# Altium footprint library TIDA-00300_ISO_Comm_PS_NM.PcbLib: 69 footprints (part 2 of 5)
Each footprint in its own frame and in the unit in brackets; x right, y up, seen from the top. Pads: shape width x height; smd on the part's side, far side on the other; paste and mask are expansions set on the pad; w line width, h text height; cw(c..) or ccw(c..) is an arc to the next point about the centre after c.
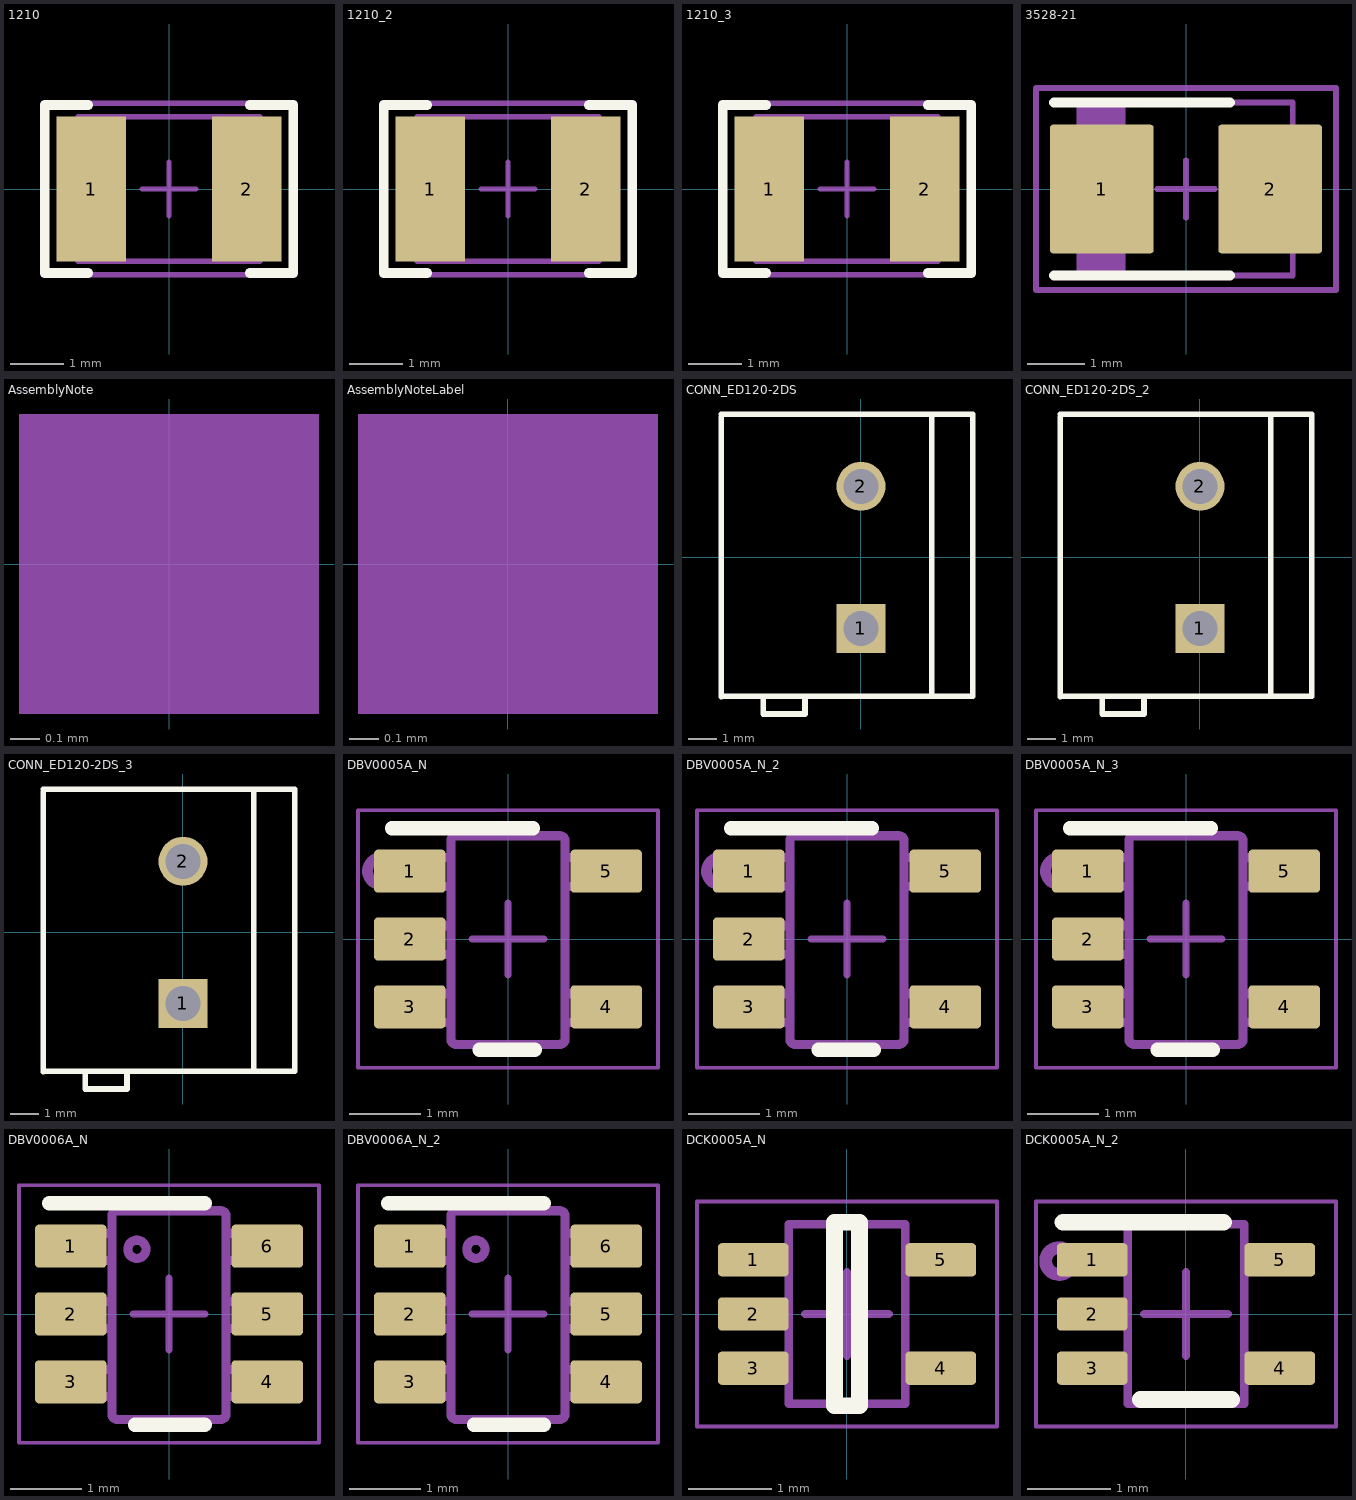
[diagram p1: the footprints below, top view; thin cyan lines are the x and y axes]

## 1210 [mm] "1210 from SM-752 data"
height 1.35
pads (2):
  rect 1.3x2.7 smd: 1(-1.45,0) 2(1.45,0)
Top Overlay:
  lines w0.178: -1.511,-1.568 -2.316,-1.568 -2.316,1.568 -1.511,1.568 ; 1.511,-1.568 2.316,-1.568 2.316,1.568 1.511,1.568
Mechanical 5:
  lines w0.1: -1.7,-1.35 -1.7,1.35 1.7,1.35 1.7,-1.35 -1.7,-1.35
  text ".Designator" at 0.229,-0.711 h0.51
Mechanical 13:
  lines w0.1: -1.2,-1.35 -1.2,1.35 ; 1.2,-1.35 1.2,1.35 ; -1.7,-1.35 1.7,-1.35 1.7,1.35 -1.7,1.35 -1.7,-1.35
Mechanical 15:
  lines w0.1: -0.5,0 0.5,0 ; 0,-0.5 0,0.5 ; -2.35,-1.6 2.35,-1.6 2.35,1.6 -2.35,1.6 -2.35,-1.6
3D body: height 1.35, standoff 0, extent 1.201,-1.349 1.699,1.349
3D body: height 1.35, standoff 0, extent -1.199,-1.349 1.199,1.349
3D body: height 1.35, standoff 0, extent -1.699,-1.349 -1.201,1.349

## 1210_2 [mm]
pads (2):
  rect 1.3x2.7 smd: 1(-1.45,0) 2(1.45,0)
Top Overlay:
  lines w0.178: -1.511,-1.568 -2.316,-1.568 -2.316,1.568 -1.511,1.568 ; 1.511,-1.568 2.316,-1.568 2.316,1.568 1.511,1.568
Mechanical 5:
  lines w0.1: -1.7,-1.35 1.7,-1.35 1.7,1.35 -1.7,1.35 -1.7,-1.35
  text ".Designator" at 0.152,-0.688 h0.51
Mechanical 13:
  lines w0.1: -1.2,-1.35 -1.2,1.35 ; 1.2,-1.35 1.2,1.35 ; -1.7,-1.35 -1.7,1.35 1.7,1.35 1.7,-1.35 -1.7,-1.35
Mechanical 15:
  lines w0.1: -0.5,0 0.5,0 ; 0,-0.5 0,0.5 ; -2.35,-1.6 -2.35,1.6 2.35,1.6 2.35,-1.6 -2.35,-1.6
3D body: height 1.35, standoff 0, extent -1.699,-1.349 -1.201,1.349
3D body: height 1.35, standoff 0, extent -1.199,-1.349 1.199,1.349
3D body: height 1.35, standoff 0, extent 1.201,-1.349 1.699,1.349

## 1210_3 [mm]
pads (2):
  rect 1.3x2.7 smd: 1(-1.45,0) 2(1.45,0)
Top Overlay:
  lines w0.178: -1.511,-1.568 -2.316,-1.568 -2.316,1.568 -1.511,1.568 ; 1.511,-1.568 2.316,-1.568 2.316,1.568 1.511,1.568
Mechanical 5:
  lines w0.1: -1.7,-1.35 1.7,-1.35 1.7,1.35 -1.7,1.35 -1.7,-1.35
  text ".Designator" at -0.254,0.298 h0.51
Mechanical 13:
  lines w0.1: -1.2,-1.35 -1.2,1.35 ; 1.2,-1.35 1.2,1.35 ; -1.7,-1.35 -1.7,1.35 1.7,1.35 1.7,-1.35 -1.7,-1.35
Mechanical 15:
  lines w0.1: -0.5,0 0.5,0 ; 0,-0.5 0,0.5 ; -2.35,-1.6 -2.35,1.6 2.35,1.6 2.35,-1.6 -2.35,-1.6
3D body: height 1.35, standoff 0, extent -1.699,-1.349 -1.201,1.349
3D body: height 1.35, standoff 0, extent -1.199,-1.349 1.199,1.349
3D body: height 1.35, standoff 0, extent 1.201,-1.349 1.699,1.349

## 3528-21 [mm] "Medium Density IPC, based on Kemet datasheet 2016-10-20"
height 2.1
pads (2):
  rrect6% 1.8x2.23 smd: 1(-1.46,0) 2(1.46,0)
Top Overlay:
  lines w0.178: -2.286,-1.5 0.762,-1.5 ; -2.286,1.5 0.762,1.5
Mechanical 5:
  rectangle: -1.85,-1.5 -1.1,1.5
  lines w0.1: -1.1,-1.5 -1.1,1.5 ; -1.85,-1.5 1.85,-1.5 1.85,1.5 -1.85,1.5 -1.85,-1.5
  text ".Designator" at -0.254,-0.292 h0.51
Mechanical 15:
  lines w0.1: -0.5,0 0.5,0 ; 0,-0.5 0,0.5 ; -2.6,-1.75 -2.6,1.75 2.6,1.75 2.6,-1.75 -2.6,-1.75
3D body "3528-21.stp": height 2.12, standoff 0.01, extent -1.85,-1.5 1.85,1.5

## AssemblyNote [mm] "Assembly Note"
Mechanical 5:
  rectangle: -0.508,-0.508 0.508,0.508
  text ".Comment" at 1.143,-0.508 h0.51
  text ".Designator" at -4.191,-0.508 h0.51

## AssemblyNoteLabel [mm] "Assembly Note for PCB Labels"
Mechanical 5:
  rectangle: -0.508,-0.508 0.508,0.508
  text "Install label in silkscreened box after final wash.  Text shall be 8 pt font.  Text shall be per the Label Table in the PDF schematic." at 1.143,-0.508 h0.51
  text ".Designator" at -4.191,-0.508 h0.51

## CONN_ED120-2DS [mm] "ONSHORE"
height 13
pads (2):
  rect 1.75x1.75 hole 1.25: 1(0,-2.54)
  round 1.75 hole 1.25: 2(0,2.54)
Top Overlay:
  lines w0.2: -5,-4.985 -5,5.015 ; -5,-4.96 4,-4.96 ; -5,5.115 4,5.115 4,-4.885 ; -3.5,-4.96 -3.5,-5.6 -2,-5.6 -2,-4.96 ; 2.525,-4.95 2.525,5.05
Mechanical 5:
  circle w0.152: c0,-2.54 r0.458
  lines w0.1: -5,-4.96 4,-4.96 ; -5,-4.885 -5,5.115 4,5.115 4,-4.885 ; -3.5,-4.96 -3.5,-5.6 -2,-5.6 -2,-4.96 ; 2.525,-4.875 2.525,5.125
  text ".Designator" at -0.184,0.432 h0.51
3D body: height 13, standoff 0, extent -3.5,-5.6 -2,-4.925
3D body: height 5.7, standoff 4.3, extent -0.875,-3.204 4.125,-1.81
3D body: height 5.7, standoff 4.3, extent -0.85,1.846 4.15,3.24
3D body: height 13.1, standoff -2.5, extent -0.496,2.041 0.5,3.039
3D body: height 13.1, standoff -2.5, extent -0.496,-3.039 0.5,-2.041
3D body: height 13, standoff 0, extent -5,-4.985 4,5.115

## CONN_ED120-2DS_2 [mm]
pads (2):
  rect 1.75x1.75 hole 1.25: 1(0,-2.54)
  round 1.75 hole 1.25: 2(0,2.54)
Top Overlay:
  lines w0.2: -5,-4.985 -5,5.015 ; -5,-4.96 4,-4.96 ; -5,5.115 4,5.115 4,-4.885 ; -3.5,-4.96 -3.5,-5.6 -2,-5.6 -2,-4.96 ; 2.525,-4.95 2.525,5.05
Mechanical 5:
  circle w0.152: c0,-2.54 r0.458
  lines w0.1: -5,-4.96 4,-4.96 ; -5,-4.885 -5,5.115 4,5.115 4,-4.885 ; -3.5,-4.96 -3.5,-5.6 -2,-5.6 -2,-4.96 ; 2.525,-4.875 2.525,5.125
  text ".Designator" at -0.159,0.279 h0.51
3D body: height 13, standoff 0, extent -5,-4.985 4,5.115
3D body: height 13.1, standoff -2.5, extent -0.496,-3.039 0.5,-2.041
3D body: height 13.1, standoff -2.5, extent -0.496,2.041 0.5,3.039
3D body: height 5.7, standoff 4.3, extent -0.85,1.846 4.15,3.24
3D body: height 5.7, standoff 4.3, extent -0.875,-3.204 4.125,-1.81
3D body: height 13, standoff 0, extent -3.5,-5.6 -2,-4.925

## CONN_ED120-2DS_3 [mm]
pads (2):
  rect 1.75x1.75 hole 1.25: 1(0,-2.54)
  round 1.75 hole 1.25: 2(0,2.54)
Top Overlay:
  lines w0.2: -5,-4.985 -5,5.015 ; -5,-4.96 4,-4.96 ; -5,5.115 4,5.115 4,-4.885 ; -3.5,-4.96 -3.5,-5.6 -2,-5.6 -2,-4.96 ; 2.525,-4.95 2.525,5.05
Mechanical 5:
  circle w0.152: c0,-2.54 r0.458
  lines w0.1: -5,-4.96 4,-4.96 ; -5,-4.885 -5,5.115 4,5.115 4,-4.885 ; -3.5,-4.96 -3.5,-5.6 -2,-5.6 -2,-4.96 ; 2.525,-4.875 2.525,5.125
  text ".Designator" at 0.484,0.254 h0.51
3D body: height 13, standoff 0, extent -3.5,-5.6 -2,-4.925
3D body: height 5.7, standoff 4.3, extent -0.875,-3.204 4.125,-1.81
3D body: height 5.7, standoff 4.3, extent -0.85,1.846 4.15,3.24
3D body: height 13.1, standoff -2.5, extent -0.496,2.041 0.5,3.039
3D body: height 13.1, standoff -2.5, extent -0.496,-3.039 0.5,-2.041
3D body: height 13, standoff 0, extent -5,-4.985 4,5.115

## DBV0005A_N [mm] "SOT23, 5-Leads, Body 2.9x1.6mm, Pitch 0.95mm, Lead Span 2.8mm, IPC Medium Density"
height 1.45
pads (5):
  rrect17% 1x0.6 smd: 1(-1.375,0.95) 2(-1.375,0) 3(-1.375,-0.95) 4(1.375,-0.95) 5(1.375,0.95)
Top Overlay:
  lines w0.2: -1.625,1.55 0.35,1.55 ; -0.4,-1.55 0.375,-1.55
Mechanical 5:
  circle w0.152: c-1.778,0.95 r0.188
  lines w0.127: -0.801,1.371 cw(c-0.725,1.37) -0.725,1.446 ; -0.801,1.37 -0.801,-1.399 -0.801,-1.4 ccw(c-0.725,-1.399) -0.725,-1.475 ; -0.801,1.37 -0.801,1.371 ; -0.725,-1.475 -0.725,-1.475 ; -0.725,-1.475 0.723,-1.475 0.724,-1.475 ccw(c0.723,-1.399) 0.799,-1.4 0.799,-1.399 0.799,1.37 ; -0.725,1.446 0.723,1.446 0.724,1.446 cw(c0.723,1.37) 0.799,1.371 ; -0.725,1.446 -0.725,1.446 ; 0.799,1.37 0.799,1.371 ; -1.423,-1.167 -1.199,-1.167 -1.105,-1.167 -1.088,-1.167 -0.835,-1.167 -0.801,-1.167 -0.801,-0.767 -0.835,-0.767 -1.088,-0.767 -1.105,-0.767 -1.199,-0.767 -1.423,-0.767 -1.423,-1.167 ; -1.423,-0.215 -1.199,-0.215 -1.105,-0.215 -1.088,-0.215 -0.835,-0.215 -0.801,-0.215 -0.801,0.186 -0.835,0.186 -1.088,0.186 -1.105,0.186 -1.199,0.186 -1.423,0.186 -1.423,-0.215 ; -1.423,0.738 -1.199,0.738 -1.105,0.738 -1.088,0.738 -0.835,0.738 -0.801,0.738 -0.801,1.138 -0.835,1.138 -1.088,1.138 -1.105,1.138 -1.199,1.138 -1.423,1.138 -1.423,0.738 ; 0.799,-1.167 0.799,-0.767 0.834,-0.767 1.087,-0.767 1.103,-0.767 1.198,-0.767 1.422,-0.767 1.422,-1.167 1.198,-1.167 1.103,-1.167 1.087,-1.167 0.834,-1.167 0.799,-1.167 ; 0.799,0.738 0.799,1.138 0.834,1.138 1.087,1.138 1.103,1.138 1.198,1.138 1.422,1.138 1.422,0.738 1.198,0.738 1.103,0.738 1.087,0.738 0.834,0.738 0.799,0.738
  text ".Designator" at 0.151,-0.584 h0.51
Mechanical 15:
  lines w0.05: -2.1,-1.8 2.1,-1.8 2.1,1.8 -2.1,1.8 -2.1,-1.8
  lines w0.1: -0.5,0 0.5,0 ; 0,-0.5 0,0.5
3D body "DBV0005A.stp": height 1.09, standoff 0, extent -1.422,-1.461 1.423,1.46

## DBV0005A_N_2 [mm]
pads (5):
  rrect17% 1x0.6 smd: 1(-1.375,0.95) 2(-1.375,0) 3(-1.375,-0.95) 4(1.375,-0.95) 5(1.375,0.95)
Top Overlay:
  lines w0.2: -1.625,1.55 0.35,1.55 ; -0.4,-1.55 0.375,-1.55
Mechanical 5:
  circle w0.152: c-1.778,0.95 r0.188
  lines w0.127: -0.801,1.371 cw(c-0.725,1.37) -0.725,1.446 ; -0.801,1.37 -0.801,-1.399 -0.801,-1.4 ccw(c-0.725,-1.399) -0.725,-1.475 ; -0.801,1.37 -0.801,1.371 ; -0.725,-1.475 -0.725,-1.475 ; -0.725,-1.475 0.723,-1.475 0.724,-1.475 ccw(c0.723,-1.399) 0.799,-1.4 0.799,-1.399 0.799,1.37 ; -0.725,1.446 0.723,1.446 0.724,1.446 cw(c0.723,1.37) 0.799,1.371 ; -0.725,1.446 -0.725,1.446 ; 0.799,1.37 0.799,1.371 ; -1.423,-1.167 -1.199,-1.167 -1.105,-1.167 -1.088,-1.167 -0.835,-1.167 -0.801,-1.167 -0.801,-0.767 -0.835,-0.767 -1.088,-0.767 -1.105,-0.767 -1.199,-0.767 -1.423,-0.767 -1.423,-1.167 ; -1.423,-0.215 -1.199,-0.215 -1.105,-0.215 -1.088,-0.215 -0.835,-0.215 -0.801,-0.215 -0.801,0.186 -0.835,0.186 -1.088,0.186 -1.105,0.186 -1.199,0.186 -1.423,0.186 -1.423,-0.215 ; -1.423,0.738 -1.199,0.738 -1.105,0.738 -1.088,0.738 -0.835,0.738 -0.801,0.738 -0.801,1.138 -0.835,1.138 -1.088,1.138 -1.105,1.138 -1.199,1.138 -1.423,1.138 -1.423,0.738 ; 0.799,-1.167 0.799,-0.767 0.834,-0.767 1.087,-0.767 1.103,-0.767 1.198,-0.767 1.422,-0.767 1.422,-1.167 1.198,-1.167 1.103,-1.167 1.087,-1.167 0.834,-1.167 0.799,-1.167 ; 0.799,0.738 0.799,1.138 0.834,1.138 1.087,1.138 1.103,1.138 1.198,1.138 1.422,1.138 1.422,0.738 1.198,0.738 1.103,0.738 1.087,0.738 0.834,0.738 0.799,0.738
  text ".Designator" at -0.33,-0.125 h0.51
Mechanical 15:
  lines w0.05: -2.1,-1.8 2.1,-1.8 2.1,1.8 -2.1,1.8 -2.1,-1.8
  lines w0.1: -0.5,0 0.5,0 ; 0,-0.5 0,0.5
3D body "DBV0005A.stp": height 1.09, standoff 0, extent -1.422,-1.461 1.423,1.46

## DBV0005A_N_3 [mm]
pads (5):
  rrect17% 1x0.6 smd: 1(-1.375,0.95) 2(-1.375,0) 3(-1.375,-0.95) 4(1.375,-0.95) 5(1.375,0.95)
Top Overlay:
  lines w0.2: -1.625,1.55 0.35,1.55 ; -0.4,-1.55 0.375,-1.55
Mechanical 5:
  circle w0.152: c-1.778,0.95 r0.188
  lines w0.127: -0.801,1.371 cw(c-0.725,1.37) -0.725,1.446 ; -0.801,1.37 -0.801,1.371 ; -0.801,1.37 -0.801,-1.399 -0.801,-1.4 ccw(c-0.725,-1.399) -0.725,-1.475 ; -0.725,-1.475 0.723,-1.475 0.724,-1.475 ccw(c0.723,-1.399) 0.799,-1.4 0.799,-1.399 0.799,1.37 ; -0.725,-1.475 -0.725,-1.475 ; -0.725,1.446 -0.725,1.446 ; -0.725,1.446 0.723,1.446 0.724,1.446 cw(c0.723,1.37) 0.799,1.371 ; 0.799,1.37 0.799,1.371 ; -1.423,-1.167 -1.423,-0.767 -1.199,-0.767 -1.105,-0.767 -1.088,-0.767 -0.835,-0.767 -0.801,-0.767 -0.801,-1.167 -0.835,-1.167 -1.088,-1.167 -1.105,-1.167 -1.199,-1.167 -1.423,-1.167 ; -1.423,-0.215 -1.423,0.186 -1.199,0.186 -1.105,0.186 -1.088,0.186 -0.835,0.186 -0.801,0.186 -0.801,-0.215 -0.835,-0.215 -1.088,-0.215 -1.105,-0.215 -1.199,-0.215 -1.423,-0.215 ; -1.423,0.738 -1.423,1.138 -1.199,1.138 -1.105,1.138 -1.088,1.138 -0.835,1.138 -0.801,1.138 -0.801,0.738 -0.835,0.738 -1.088,0.738 -1.105,0.738 -1.199,0.738 -1.423,0.738 ; 0.799,-1.167 0.834,-1.167 1.087,-1.167 1.103,-1.167 1.198,-1.167 1.422,-1.167 1.422,-0.767 1.198,-0.767 1.103,-0.767 1.087,-0.767 0.834,-0.767 0.799,-0.767 0.799,-1.167 ; 0.799,0.738 0.834,0.738 1.087,0.738 1.103,0.738 1.198,0.738 1.422,0.738 1.422,1.138 1.198,1.138 1.103,1.138 1.087,1.138 0.834,1.138 0.799,1.138 0.799,0.738
  text ".Designator" at -0.412,-0.184 h0.51
Mechanical 15:
  lines w0.05: -2.1,-1.8 -2.1,1.8 2.1,1.8 2.1,-1.8 -2.1,-1.8
  lines w0.1: -0.5,0 0.5,0 ; 0,-0.5 0,0.5
3D body "DBV0005A.stp": height 1.09, standoff 0, extent -1.422,-1.461 1.423,1.46

## DBV0006A_N [mm] "SOT23, 6-Leads, Body 2.9x1.6mm, Pitch 0.95mm, Lead Span 2.8mm, IPC Medium Density"
height 1.45
pads (6):
  rrect17% 1x0.6 smd: 1(-1.375,0.95) 2(-1.375,0) 3(-1.375,-0.95) 4(1.375,-0.95) 5(1.375,0) 6(1.375,0.95)
Top Overlay:
  lines w0.2: -1.675,1.55 0.5,1.55 ; -0.475,-1.55 0.5,-1.55
Mechanical 5:
  lines w0.127: 0.724,-1.475 ccw(c0.723,-1.399) 0.8,-1.399 0.8,1.37 ccw(c0.723,1.37) 0.724,1.446 ; 0.723,-1.475 0.724,-1.475 ; 0.723,-1.475 -0.724,-1.475 -0.725,-1.475 cw(c-0.724,-1.399) -0.801,-1.399 -0.801,1.37 cw(c-0.724,1.37) -0.725,1.446 -0.724,1.446 0.723,1.446 ; 0.723,1.446 0.724,1.446 ; -1.423,-1.154 -1.206,-1.154 -1.113,-1.154 -1.081,-1.154 -0.828,-1.154 -0.801,-1.154 -0.801,-0.78 -0.828,-0.78 -1.081,-0.78 -1.113,-0.78 -1.206,-0.78 -1.423,-0.78 -1.423,-1.154 ; -1.423,-0.202 -1.206,-0.202 -1.113,-0.202 -1.081,-0.202 -0.828,-0.202 -0.801,-0.202 -0.801,0.173 -0.828,0.173 -1.081,0.173 -1.113,0.173 -1.206,0.173 -1.423,0.173 -1.423,-0.202 ; -1.423,0.751 -1.206,0.751 -1.113,0.751 -1.081,0.751 -0.828,0.751 -0.801,0.751 -0.801,1.125 -0.828,1.125 -1.081,1.125 -1.113,1.125 -1.206,1.125 -1.423,1.125 -1.423,0.751 ; -0.577,0.906 cw(c-0.45,0.906) -0.323,0.906 cw(c-0.45,0.906) -0.577,0.906 ; 0.8,-1.154 0.827,-1.154 1.08,-1.154 1.112,-1.154 1.205,-1.154 1.422,-1.154 1.422,-0.78 1.205,-0.78 1.112,-0.78 1.08,-0.78 0.827,-0.78 0.8,-0.78 0.8,-1.154 ; 0.8,-0.202 0.827,-0.202 1.08,-0.202 1.112,-0.202 1.205,-0.202 1.422,-0.202 1.422,0.173 1.205,0.173 1.112,0.173 1.08,0.173 0.827,0.173 0.8,0.173 0.8,-0.202 ; 0.8,0.751 0.827,0.751 1.08,0.751 1.112,0.751 1.205,0.751 1.422,0.751 1.422,1.125 1.205,1.125 1.112,1.125 1.08,1.125 0.827,1.125 0.8,1.125 0.8,0.751
  text ".Designator" at -0.108,0.61 h0.51
Mechanical 15:
  lines w0.05: -2.1,-1.8 2.1,-1.8 2.1,1.8 -2.1,1.8 -2.1,-1.8
  lines w0.1: -0.5,0 0.5,0 ; 0,-0.5 0,0.5
3D body "DBV0006A.stp": height 1.12, standoff 0, extent -1.422,-1.461 1.423,1.46

## DBV0006A_N_2 [mm]
pads (6):
  rrect17% 1x0.6 smd: 1(-1.375,0.95) 2(-1.375,0) 3(-1.375,-0.95) 4(1.375,-0.95) 5(1.375,0) 6(1.375,0.95)
Top Overlay:
  lines w0.2: -1.675,1.55 0.5,1.55 ; -0.475,-1.55 0.5,-1.55
Mechanical 5:
  lines w0.127: 0.724,-1.475 ccw(c0.723,-1.399) 0.8,-1.399 0.8,1.37 ccw(c0.723,1.37) 0.724,1.446 ; 0.723,-1.475 -0.724,-1.475 -0.725,-1.475 cw(c-0.724,-1.399) -0.801,-1.399 -0.801,1.37 cw(c-0.724,1.37) -0.725,1.446 -0.724,1.446 0.723,1.446 ; 0.723,-1.475 0.724,-1.475 ; 0.723,1.446 0.724,1.446 ; -1.423,-1.154 -1.423,-0.78 -1.206,-0.78 -1.113,-0.78 -1.081,-0.78 -0.828,-0.78 -0.801,-0.78 -0.801,-1.154 -0.828,-1.154 -1.081,-1.154 -1.113,-1.154 -1.206,-1.154 -1.423,-1.154 ; -1.423,-0.202 -1.423,0.173 -1.206,0.173 -1.113,0.173 -1.081,0.173 -0.828,0.173 -0.801,0.173 -0.801,-0.202 -0.828,-0.202 -1.081,-0.202 -1.113,-0.202 -1.206,-0.202 -1.423,-0.202 ; -1.423,0.751 -1.423,1.125 -1.206,1.125 -1.113,1.125 -1.081,1.125 -0.828,1.125 -0.801,1.125 -0.801,0.751 -0.828,0.751 -1.081,0.751 -1.113,0.751 -1.206,0.751 -1.423,0.751 ; -0.577,0.906 ccw(c-0.45,0.906) -0.323,0.906 ccw(c-0.45,0.906) -0.577,0.906 ; 0.8,-1.154 0.8,-0.78 0.827,-0.78 1.08,-0.78 1.112,-0.78 1.205,-0.78 1.422,-0.78 1.422,-1.154 1.205,-1.154 1.112,-1.154 1.08,-1.154 0.827,-1.154 0.8,-1.154 ; 0.8,-0.202 0.8,0.173 0.827,0.173 1.08,0.173 1.112,0.173 1.205,0.173 1.422,0.173 1.422,-0.202 1.205,-0.202 1.112,-0.202 1.08,-0.202 0.827,-0.202 0.8,-0.202 ; 0.8,0.751 0.8,1.125 0.827,1.125 1.08,1.125 1.112,1.125 1.205,1.125 1.422,1.125 1.422,0.751 1.205,0.751 1.112,0.751 1.08,0.751 0.827,0.751 0.8,0.751
  text ".Designator" at 0.298,0.229 h0.51
Mechanical 15:
  lines w0.05: -2.1,-1.8 -2.1,1.8 2.1,1.8 2.1,-1.8 -2.1,-1.8
  lines w0.1: -0.5,0 0.5,0 ; 0,-0.5 0,0.5
3D body "DBV0006A.stp": height 1.12, standoff 0, extent -1.422,-1.461 1.423,1.46

## DCK0005A_N [mm] "SOT353, 5-Leads, Body 2x1.3mm, Pitch 0.65mm, Lead Span 2.1mm, IPC Medium Density"
height 1.1
pads (5):
  rrect25% 0.85x0.4 smd: 1(-1.125,0.65) 2(-1.125,0) 3(-1.125,-0.65) 4(1.125,-0.65) 5(1.125,0.65)
Top Overlay:
  lines w0.2: -0.15,-1.1 0.15,-1.1 0.15,1.1 -0.15,1.1 -0.15,-1.1
Mechanical 5:
  lines w0.1: -0.7,-1.075 -0.7,1.075 0.7,1.075 0.7,-1.075 -0.7,-1.075
  lines w0.127: -0.865,0.762 -0.853,0.762 ; -0.711,-0.763 -0.853,-0.763 -0.865,-0.763 -0.959,-0.763 -1.143,-0.763 -1.143,-0.538 -0.959,-0.538 -0.865,-0.538 -0.853,-0.538 -0.711,-0.538 ; -0.711,-0.113 -0.853,-0.113 -0.865,-0.113 -0.959,-0.113 -1.143,-0.113 -1.143,0.112 -0.959,0.112 -0.865,0.112 -0.853,0.112 -0.711,0.112 ; -0.711,0.537 -0.853,0.537 -0.865,0.537 -0.959,0.537 -1.143,0.537 -1.143,0.762 -0.959,0.762 -0.711,0.762 ; 0.711,-0.763 0.847,-0.763 0.859,-0.763 0.953,-0.763 1.137,-0.763 1.137,-0.538 0.953,-0.538 0.859,-0.538 0.847,-0.538 0.711,-0.538 ; 0.711,0.537 0.847,0.537 0.859,0.537 0.953,0.537 1.137,0.537 1.137,0.762 0.953,0.762 0.859,0.762 0.847,0.762 0.711,0.762
  text ".Designator" at -0.216,0.623 h0.51
Mechanical 15:
  lines w0.05: -1.8,-1.35 -1.8,1.35 1.8,1.35 1.8,-1.35 -1.8,-1.35
  lines w0.1: -0.5,0 0.5,0 ; 0,-0.5 0,0.5
3D body "DCK0005A.stp": height 0.95, standoff 0, extent -1.14,-1 1.14,1

## DCK0005A_N_2 [mm]
pads (5):
  rrect25% 0.85x0.4 smd: 1(-1.125,0.65) 2(-1.125,0) 3(-1.125,-0.65) 4(1.125,-0.65) 5(1.125,0.65)
Top Overlay:
  lines w0.2: -1.475,1.1 0.45,1.1 ; -0.55,-1.025 0.55,-1.025
Mechanical 5:
  circle w0.152: c-1.524,0.635 r0.16
  lines w0.1: -0.7,-1.075 -0.7,1.075 0.7,1.075 0.7,-1.075 -0.7,-1.075
  lines w0.127: -0.865,0.762 -0.853,0.762 ; -0.711,-0.763 -0.853,-0.763 -0.865,-0.763 -0.959,-0.763 -1.143,-0.763 -1.143,-0.538 -0.959,-0.538 -0.865,-0.538 -0.853,-0.538 -0.711,-0.538 ; -0.711,-0.113 -0.853,-0.113 -0.865,-0.113 -0.959,-0.113 -1.143,-0.113 -1.143,0.112 -0.959,0.112 -0.865,0.112 -0.853,0.112 -0.711,0.112 ; -0.711,0.537 -0.853,0.537 -0.865,0.537 -0.959,0.537 -1.143,0.537 -1.143,0.762 -0.959,0.762 -0.711,0.762 ; 0.711,-0.763 0.847,-0.763 0.859,-0.763 0.953,-0.763 1.137,-0.763 1.137,-0.538 0.953,-0.538 0.859,-0.538 0.847,-0.538 0.711,-0.538 ; 0.711,0.537 0.847,0.537 0.859,0.537 0.953,0.537 1.137,0.537 1.137,0.762 0.953,0.762 0.859,0.762 0.847,0.762 0.711,0.762
  text ".Designator" at 0.152,-0.406 h0.51
Mechanical 15:
  lines w0.05: -1.8,-1.35 -1.8,1.35 1.8,1.35 1.8,-1.35 -1.8,-1.35
  lines w0.1: -0.5,0 0.5,0 ; 0,-0.5 0,0.5
3D body "DCK0005A.stp": height 0.95, standoff 0, extent -1.14,-1 1.14,1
